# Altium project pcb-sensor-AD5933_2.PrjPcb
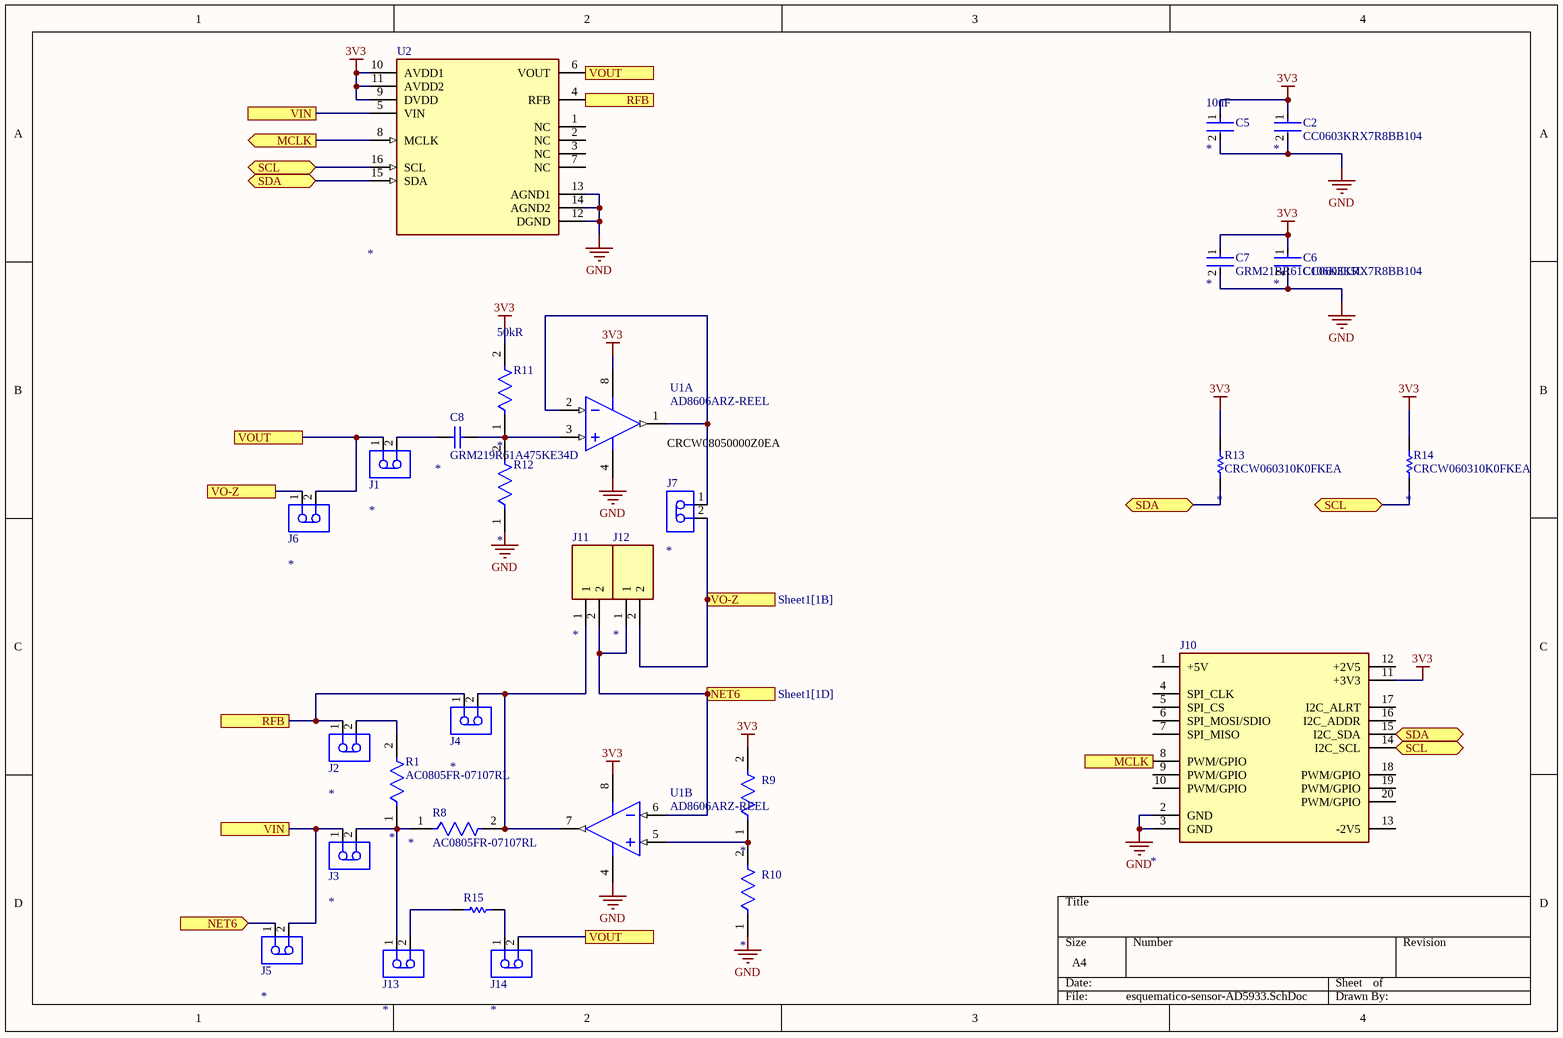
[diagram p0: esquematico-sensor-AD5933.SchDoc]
1 sheet, 28 parts. Net scope: flat (ports and power ports of the same name join across sheets).
Board file: pcb-sensor-AD5933.PcbDoc

## Sheet esquematico-sensor-AD5933.SchDoc
size A4; SheetNumber: 1; SheetTotal: 1

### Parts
C2  CC0603KRX7R8BB104  [FP-CC0603-DA-MFG]
C5  Capacitance: 10uF  [FP-GRM21B-0_1-IPC_C]  (hidden comment: GRM21BR61C106KE15L)
C6  CC0603KRX7R8BB104  [FP-CC0603-DA-MFG]
C7  GRM21BR61C106KE15L  [FP-GRM21B-0_1-IPC_C]
C8  GRM219R61A475KE34D  [CAPC2013X95X45LL10T25]
J1  (no value)  [TECO-640456-2_V]
J2  (no value)  [TECO-640456-2_V]
J3  (no value)  [TECO-640456-2_V]
J4  (no value)  [TECO-640456-2_V]
J5  (no value)  [TECO-640456-2_V]
J6  (no value)  [TECO-640456-2_V]
J7  (no value)  [TECO-640456-2_V]
J10  10129382-920002BLF  [Base Board Modular Connector (MALE)]  (value not drawn)
J11  (no value)  [Terminal Block 2-position]
J12  TB0011-350-02BE  [Terminal Block 2-position]  (value not drawn)
J13  (no value)  [TECO-640456-2_V]
J14  (no value)  [TECO-640456-2_V]
R1  AC0805FR-07107RL  [FP-AC0805-MFG]
R8  AC0805FR-07107RL  [FP-AC0805-MFG]
R9  (no value)  [FP-TNPU0603-e3-MFG]
R10  (no value)  [FP-TNPU0603-e3-MFG]
R11  Resistance: 50kR  [FP-TNPU0603-e3-MFG]
R12  (no value)  [FP-TNPU0603-e3-MFG]
R13  CRCW060310K0FKEA  [RESC1609X50X30NL8T20]
R14  CRCW060310K0FKEA  [RESC1609X50X30NL8T20]
R15  CRCW08050000Z0EA  [RESC2013X50X30LL20T20]  (value not drawn)
U1  AD8606ARZ-REEL  [ADI-R-8_L]  (parts A,B of 2)
U2  AD5933WYRSZ-REEL7  [FP-RS-16-IPC_A]  (value not drawn)

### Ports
MCLK (in, see Sheet1[1A]), MCLK (out, see Sheet1[3C]), NET6 (in, see Sheet1[2C]), NET6 (out, see Sheet1[1D]), RFB (see Sheet1[1C]), RFB (see Sheet1[2A]), SCL (bidir, see Sheet1[1A], Sheet1[4B]), SCL (bidir, see Sheet1[1A], Sheet1[4C]), SCL (bidir, see Sheet1[4B], Sheet1[4C]), SDA (bidir, see Sheet1[1A], Sheet1[3B]), SDA (bidir, see Sheet1[1A], Sheet1[4C]), SDA (bidir, see Sheet1[3B], Sheet1[4C]), VIN (see Sheet1[1A]), VIN (see Sheet1[1D]), VO-Z (see Sheet1[1B]), VO-Z (see Sheet1[2C]), VOUT (see Sheet1[1B], Sheet1[2A]), VOUT (see Sheet1[1B], Sheet1[2D]), VOUT (see Sheet1[2A], Sheet1[2D])

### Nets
3V3: C2.1 C5.1 C6.1 C7.1 J10.11(+3V3) R9.2 R11.2 R13.1 R14.2 U1.8(+V) U2.9(DVDD) U2.10(AVDD1) U2.11(AVDD2)
GND: C2.2 C5.2 C6.2 C7.2 J10.2(GND) J10.3(GND) R10.1 R12.1 U1.4(-V) U2.12(DGND) U2.13(AGND1) U2.14(AGND2)
NetC8_1: C8.1 J1.2
NetC8_2: C8.2 R11.1 R12.2 U1.3(+IN_A)
NetJ1_1: J1.1 J6.2 J14.2 U2.6(VOUT) ; port VOUT
NetJ2_1: J2.1 J4.1 U2.4(RFB) ; port RFB
NetJ2_2: J2.2 R1.2
NetJ3_1: J3.1 J5.2 U2.5(VIN) ; port VIN
NetJ3_2: J3.2 J13.1 R1.1 R8.1
NetJ4_2: J4.2 J11.1 R8.2 U1.7(OUT_B)
NetJ5_1: J5.1 J11.2 J12.1 U1.6(-IN_B) ; port NET6
NetJ6_1: J6.1 J7.2 J12.2 ; port VO-Z
NetJ7_1: J7.1 U1.1(OUT_A) U1.2(-IN_A)
NetJ10_8: J10.8(PWM/GPIO) U2.8(MCLK) ; port MCLK
NetJ10_14: J10.14(I2C_SCL) R14.1 U2.16(SCL) ; port SCL
NetJ10_15: J10.15(I2C_SDA) R13.2 U2.15(SDA) ; port SDA
NetJ13_2: J13.2 R15.1
NetJ14_1: J14.1 R15.2
NetR9_1: R9.1 R10.2 U1.5(+IN_B)

Not connected (* = marked no-connect by the designer): J10 1(+5V) 4(SPI_CLK) 5(SPI_CS) 6(SPI_MOSI/SDIO) 7(SPI_MISO) 9(PWM/GPIO) 10(PWM/GPIO) 12(+2V5) 13(-2V5) 16(I2C_ADDR) 17(I2C_ALRT) 18(PWM/GPIO) 19(PWM/GPIO) 20(PWM/GPIO); U2 1(NC) 2(NC) 3(NC) 7(NC)

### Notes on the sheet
- (near U1) CRCW08050000Z0EA

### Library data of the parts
C2 C6 = CMP-03422-000234-1: CAP CER 0.1UF 25V X7R 0603; Manufacturer: YAGEO; Capacitance: 100 nF; Tolerance: 0.1; Temperature Coefficient: 15%; Material: Ceramic; Value: 100 nF
C5 C7 = CMP-2007-03453-2: Chip Multilayer Ceramic Capacitors for General Purpose, 0805, 10uF, X5R, 15%, 10%, 16V
C8 = CMP-2007-00178-1: Manufacturer: Murata
J1-J7 J13 J14 = CMP-2000-05417-1: Male Header, Pitch 2.54 mm, 1 x 2 Position, Height 10.49 mm, Tail Length 3.556 mm, -55 to 105 degC, RoHS, Bulk; Manufacturer: TE Connectivity; Standards: RoHSCompliant,ELVCompliant,UL94V-0; Material, Housing: Polyester; Agency Approvals: CSA,UL; Brand/Series: MTA-100Series; Contact Centerline Spacing: 0.100 / in.; Material, Contact: CopperAlloy; Current, Rating: 5 / A; Color, Housing: White; Contact Termination Area Plating: Tin; Special Features: Pinstrip; Number of Positions: 2; Pin Spacing: 0.1 / "; Temperature, Operating: -55to+105 / degC; Angle: Straight; Mount Angle: Vertical; Connector Type: MTA-100; Primary Type: InterconnectSystem; Voltage, Rating: 250 / V; Mounting Hole Size: 0.04 / "
J10 = Base Board Modular Connector (MALE)
J11 J12 = TB0011-350-02BE: Fixed Terminal Blocks 2 Poles, Screw Type, Horizontal, 3.50 Pitch, 24-18 (AWG), Blue, Terminal Block Connector
R1 R8 = CMP-03412-037308-1: Res SMD 107 Ohm 1% 1/8W 0805; Manufacturer: Yageo; Tolerance: 0.01; Value: 107Ω; Automotive Grade: Grade 0; Voltage Rating: 150V
R9 R10 R12 = CMP-02407-013067-1: RES SMD 50K OHM 0.02% 1/10W 0603; Temperature Coefficient: 5ppm/°C; Max Power Dissipation: 100mW; Resistance: 50kR
R11 = CMP-02407-013067-1: RES SMD 50K OHM 0.02% 1/10W 0603; Temperature Coefficient: 5ppm/°C; Max Power Dissipation: 100mW
R13 R14 = CMP-1666-00005-4: Chip Resistor, 10 KOhm, +/- 1%, 100 mW, -55 to 155 degC, 0603 (1608 Metric), RoHS, Tape and Reel; Manufacturer: Vishay Semiconductor; Voltage Rating: 75 V
R15 = CMP-2001-04896-1: Manufacturer: Vishay Dale
U1 = CMP-0384-01320-2: Double Channel Wide Bandwidth Operational Amplifier, 10 MHz BW, 5 V/us SR, Industrial, 8-pin SOIC (R-8), Reel; Generic Part Number: AD8606; Manufacturer: Analog Devices; Amplifiers Per Package: 2; Input Bias Current: 200fA; V Span Max: 6V; V Span Min: 2.7V; Input Offset Voltage: 20uV; Small Signal Bandwidth: 10MHz; Slew Rate: 5V/us; Iq/Amp: 1.2mA
U2 = CMP-09111-000002-1: 12BIT 1 MSPS, IMPEDANCE CONVERTE; Sampling Rate: 1MS/s; Nominal Supply Current: 15mA; Resolution: 12b; Frequency: 16.776MHz; Accuracy: 0.5%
